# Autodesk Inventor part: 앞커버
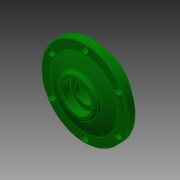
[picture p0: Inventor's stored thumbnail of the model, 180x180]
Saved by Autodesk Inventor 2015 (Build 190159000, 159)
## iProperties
Created: 2016-05
Part Number: 앞커버
Document SubType Name: Modeling
Designer: mduedu
Density: 2.71 g/cm^3
Material: 알루미늄 6061
Appearance: 진녹색
Author: mduedu
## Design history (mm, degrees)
sketch "스케치1"
  geometry: C1 r 31 at (0, 0); C2 r 45 at (0, 0); 1 further point
  constraints: 2 centre point, 2 coincident
  dimensions: "d33" = 90 diameter of C2; "d34" = 62 diameter of C1
extrude "돌출1" new body sketch "스케치1" distance "d0" = 8; taper "d1" = 0 deg
extrude "돌출2" join sketch "스케치1" distance "d2" = 8; taper "d3" = 0 deg; dims "d35" = 12, "d36" = 0
sketch "스케치5"
  geometry: L1 (-45, 8)-(45, 8) reference; L2 (0, 0)-(0, 15); L3 (-45, 0)-(45, 0) reference; L4 (35, 8)-(0, 8); A1 r 91 centre (0, -76) between (35, 8) and (0, 15)
  constraints: 4 end point, 3 point on line, 2 point on circle, 1 centre point, 1 midpoint, 1 perpendicular
  dimensions: "d37" = 35 distance from line of L2 L4.start; "d39" = 7 distance from line of L1 L2.end
revolve "회전2" sketch "스케치5" stored, may be unused: angle "d40" = 90 deg
node "작업 평면1"
sketch "스케치6"
  geometry: C1 r 20 at (0, 0); 1 further point
  constraints: 1 centre point, 1 coincident
  dimensions: "d42" = 40 diameter of C1
extrude "돌출4" join sketch "스케치6" stored distance "d43" = 10; taper "d44" = 0 deg
sketch "스케치4"
  geometry: L1 (0, -12)-(0, 16); L2 (-20, -12)-(-20, 0); L3 (-20, 0)-(-15, 0); L4 (-15, 0)-(-15, 3); L5 (-15, 3)-(-10, 3); L6 (-10, 3)-(-10, 7.5); L7 (-10, 7.5)-(-15, 7.5); L8 (-15, 7.5)-(-15, 16); L9 (31, -12)-(-31, -12) reference; L10 (-20, 16)-(20, 16) reference; 1 further point
  constraints: 16 end point, 6 parallel, 3 point on line, 2 midpoint, 1 perpendicular, 1 vertical
  dimensions: "d15" = 40 diameter of L2 L1; "d16" = 30 diameter of L8 L1; "d18" = 12 distance of L2.start L2.end; "d19" = 3 distance of L3.end L4.end; "d20" = 30 diameter of L4 L1; "d21" = 20 diameter of L6 L1; "d45" = 8.5 distance of L7.end L8.end
revolve "회전1" sketch "스케치4" stored, may be unused: angle "d22" = 90 deg
fillet "모깎기2" dims "d23" = 3
fillet "모깎기3" dims "d24" = 0.3
chamfer "모따기2" distance "d46" = 1; stored, may be unused: second distance "d47" = 2, angle "d48" = 45 deg
fillet "모깎기4" dims "d49" = 3
fillet "모깎기5" dims "d50" = 3
fillet "모깎기6" dims "d51" = 1
sketch "스케치7" dims "d52" = 80
  geometry: C1 r 35.595 at (0, 0) reference; C2 r 44 at (0, 0) reference; 7 further points
  constraints: 2 vertical alignment, 1 coincident, 9 other
  dimensions: "d55" = 360 deg dimension on C1.centre point (0, 40) (derived)
sketch "스케치8"
  geometry: 6 further points
  constraints: 6 other
hole "구멍2" sketch "스케치8" at (-34.641, 20), (-34.641, -20), (0, -40), (34.641, -20), (34.641, 20), (0, 40) diameter "d57" = 4.5; stored, may be unused: countersink angle "d61" = 90 deg, drill point angle "d63" = 0 deg; dims "d58" = 6, "d59" = 8, "d60" = 4.6, "d62" = 8
chamfer "모따기3" distance "d64" = 0.8; stored, may be unused: second distance "d65" = 2, angle "d66" = 30 deg
node "솔리드1"
other parameters: "d41" = 8
